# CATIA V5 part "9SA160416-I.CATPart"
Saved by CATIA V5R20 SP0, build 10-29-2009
Part number: 9SA160416-I
Revision: ANY
Definition: UNKNOWN
Nomenclature: 9SA160416-I
Source: Unknown
Bounding box of the stored display mesh (mm): x -4.95 to 4.95, y -14 to 3, z -4.95 to 4.95
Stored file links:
  C:\Users\Utente\Desktop\IO LAVORO\3D X SITO CF\CUMSA\3D files SA\SA 160416\9SA160416-I.CATPart
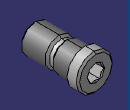
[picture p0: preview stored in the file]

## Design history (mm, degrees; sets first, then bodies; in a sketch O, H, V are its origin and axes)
Body1 "Chaflán3" (main body)
  Solid1: solid without history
